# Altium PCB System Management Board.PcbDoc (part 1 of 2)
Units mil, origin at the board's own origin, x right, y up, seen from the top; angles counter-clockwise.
Board outline 5905.51 x 4330.71 mil, 4 copper layers (F.Cu, In1.Cu, In2.Cu, B.Cu); 241 components, 148 nets, 704 pads, 16 vias.
Unrouted connection lines stored in the file: 314.
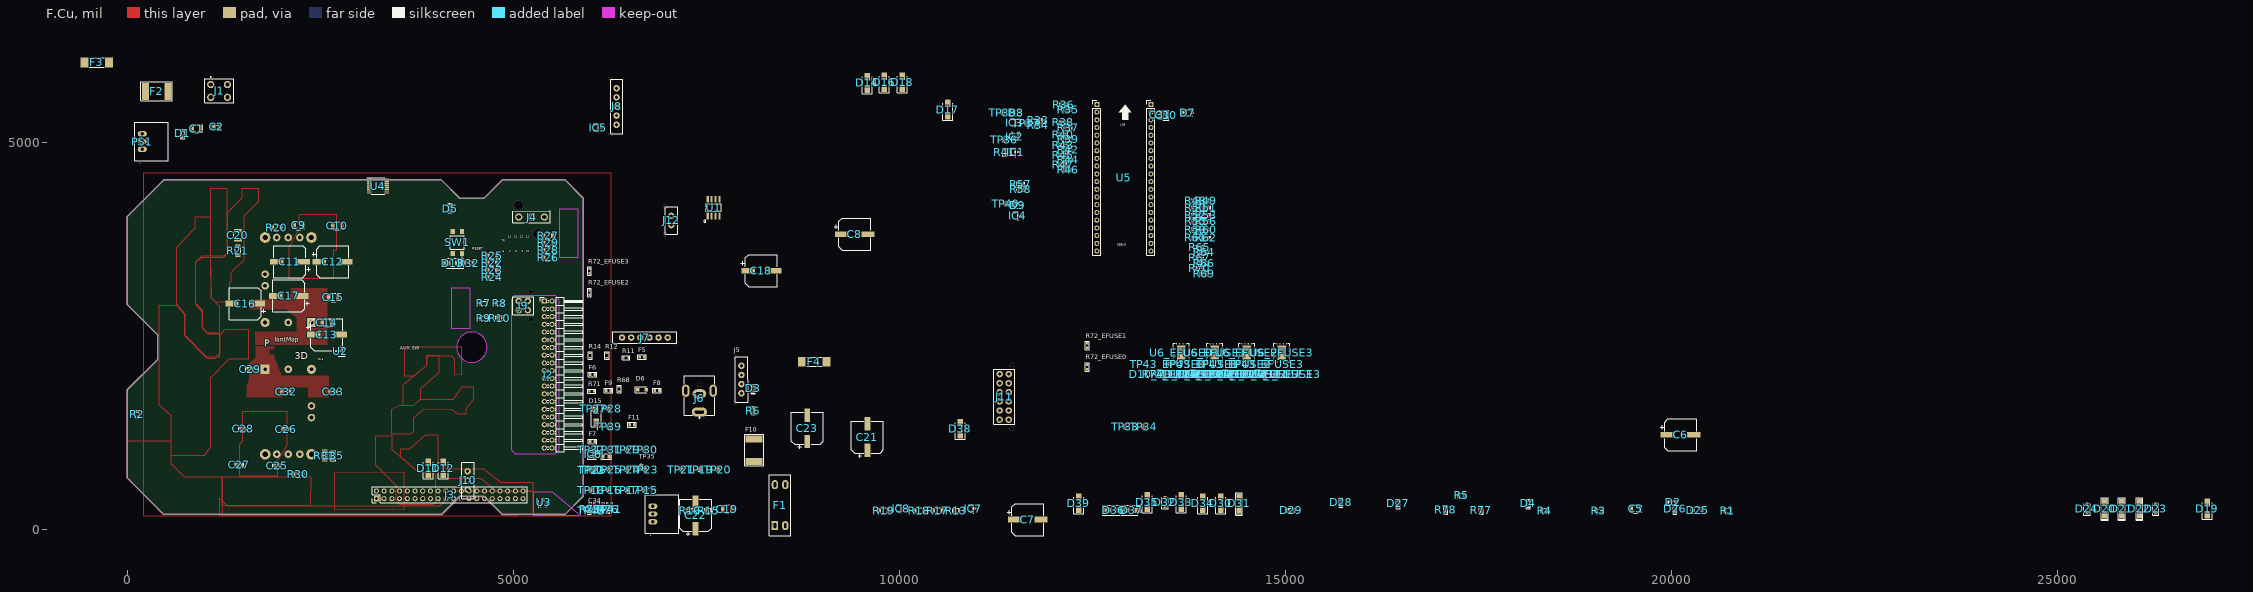
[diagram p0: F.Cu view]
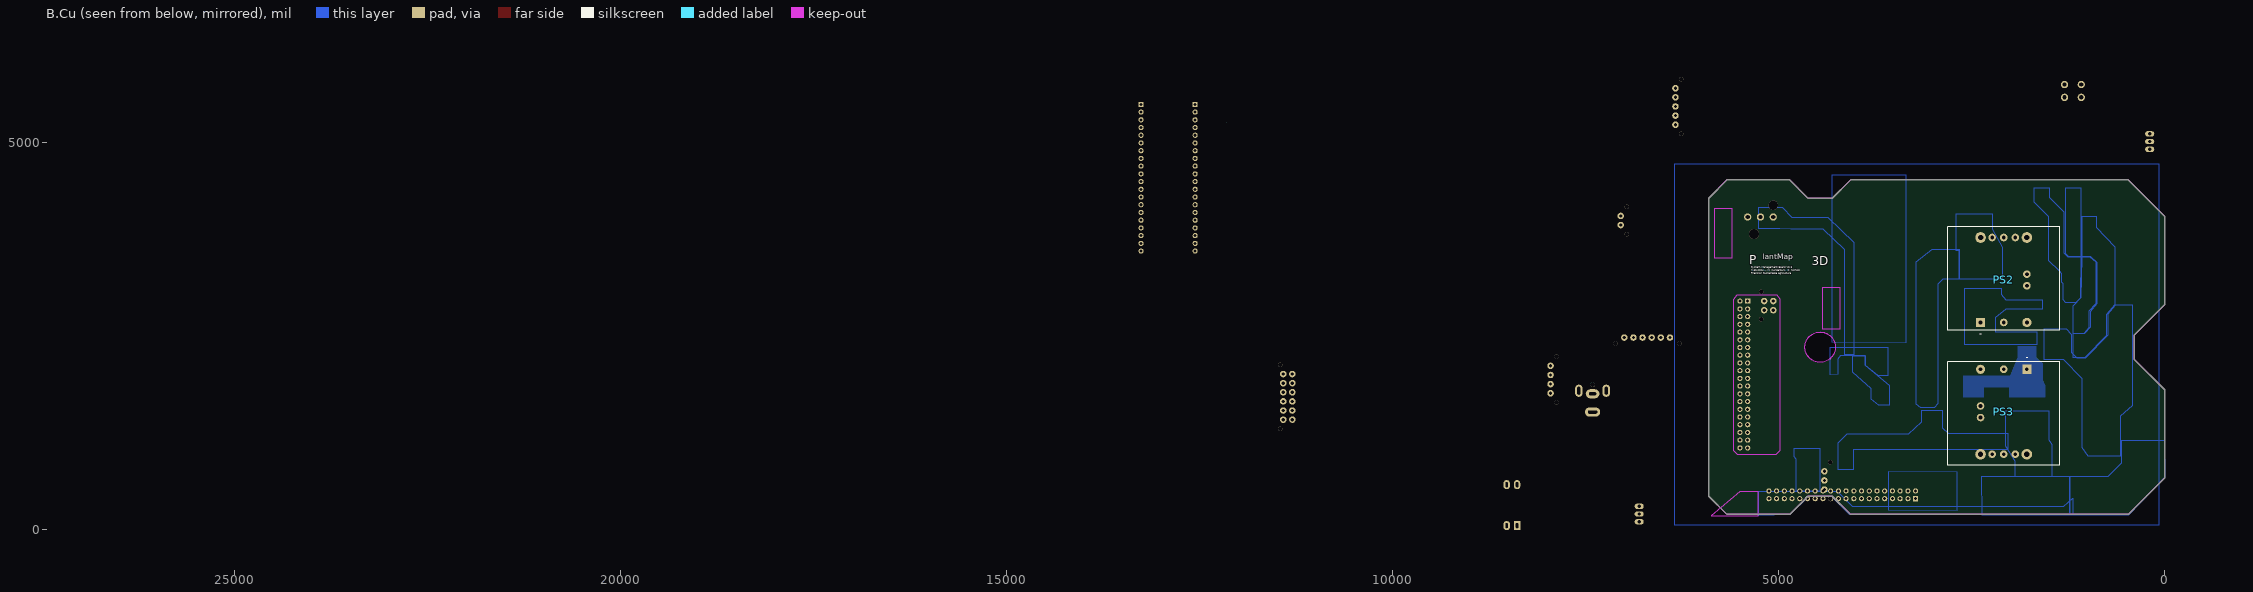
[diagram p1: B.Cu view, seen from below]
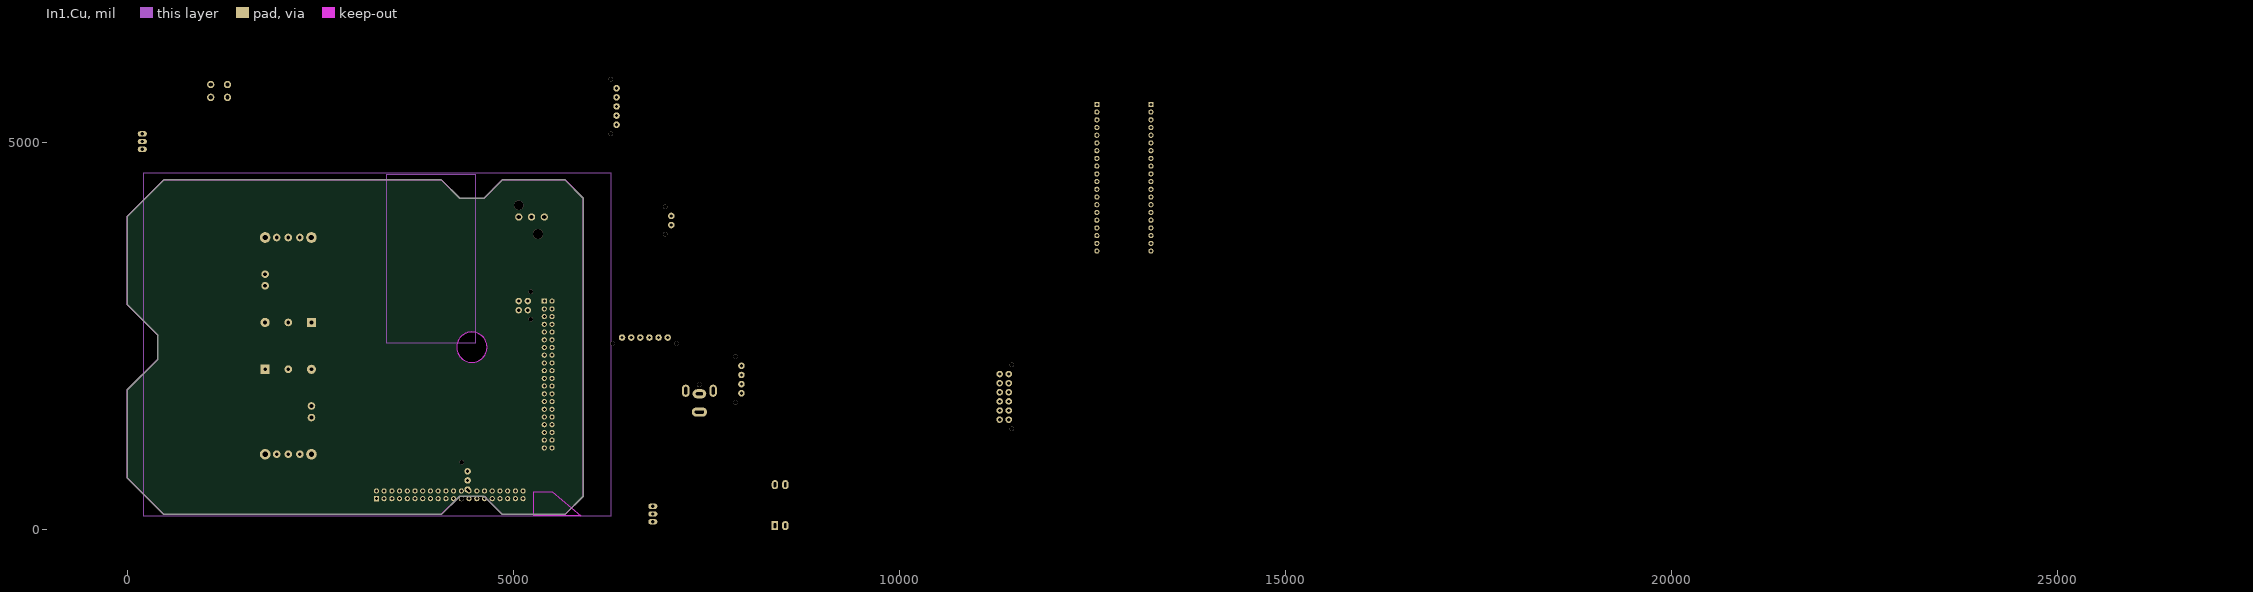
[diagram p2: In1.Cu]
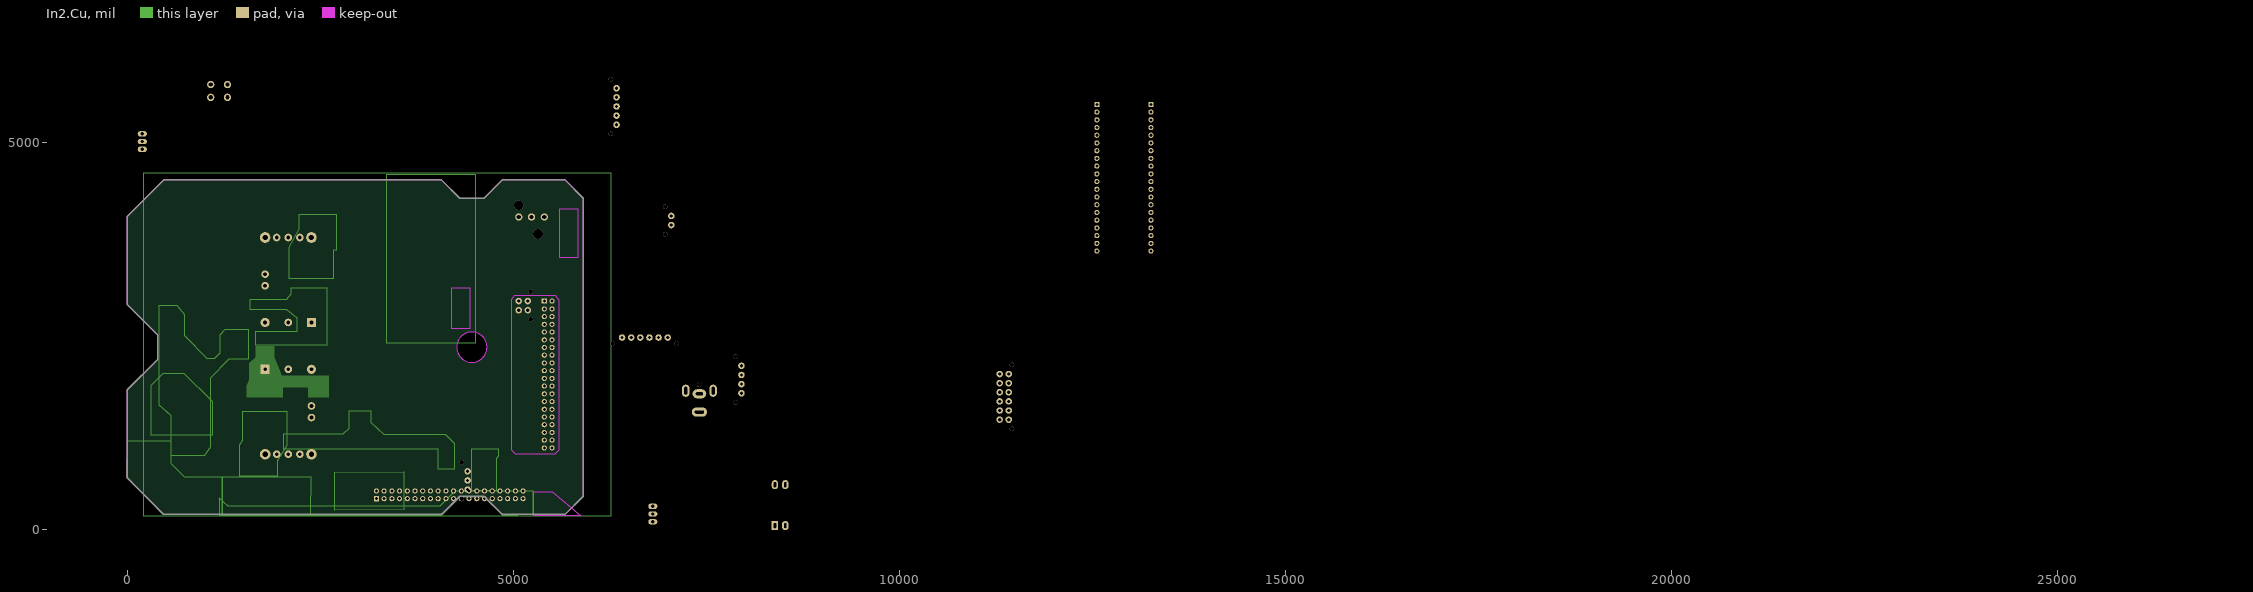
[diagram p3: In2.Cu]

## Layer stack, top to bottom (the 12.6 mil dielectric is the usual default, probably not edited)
F.Mask: solder mask 0.4, Solder Resist, Dk 3.5
F.Cu: signal copper 1.4
Dielectric 1: dielectric 12.6, FR-4, Dk 4.8
In1.Cu: signal copper 1.4
Dielectric2: dielectric 12.6, FR-4, Dk 4.8
In2.Cu: signal copper 1.4
Dielectric3: dielectric 12.6, FR-4, Dk 4.8
B.Cu: signal copper 1.4
B.Mask: solder mask 0.4, Solder Resist, Dk 3.5

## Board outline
4307.02,426.04 4621.98,426.04 4858.2,189.82 5671.85,189.82 5908.07,426.04 5908.07,4284.31 5671.85,4520.53 4858.2,4520.53 4621.98,4284.31 4307.02,4284.31 4070.8,4520.53 475,4520.53 2.56,4048.09 2.56,2906.36 396.26,2512.65 396.26,2197.69 2.56,1803.99 2.56,662.26 475,189.82 4070.8,189.82 4307.02,426.04
cut-out: 4267.23,2355.17 4268.92,2329.43 4273.95,2304.12 4282.24,2279.68 4293.66,2256.54 4307.99,2235.08 4325.01,2215.68 4344.41,2198.67 4365.86,2184.33 4389.01,2172.92 4413.44,2164.62 4438.75,2159.59 4464.5,2157.9 4490.25,2159.59 4515.56,2164.62 4539.99,2172.92 4563.14,2184.33 4584.59,2198.67 4603.99,2215.68 4621.01,2235.08 4635.34,2256.54 4646.76,2279.68 4655.05,2304.12 4660.09,2329.43 4661.77,2355.17 4660.09,2380.92 4655.05,2406.23 4646.76,2430.67 4635.34,2453.81 4621.01,2475.27 4603.99,2494.67 4584.59,2511.68 4563.14,2526.02 4539.99,2537.43 4515.56,2545.73 4490.25,2550.76 4464.5,2552.45 4438.75,2550.76 4413.44,2545.73 4389.01,2537.43 4365.86,2526.02 4344.41,2511.68 4325.01,2494.67 4307.99,2475.27 4293.66,2453.81 4282.24,2430.67 4273.95,2406.23 4268.92,2380.92 4267.23,2355.17

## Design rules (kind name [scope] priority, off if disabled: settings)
Clearance "Clearence 0.254_Polygon" [InNamedPolygon('F.Cu-/5V Intermediate') OR InNamedPolygon('F.Cu-/i3_Vin') OR InNamedPolygon('F.Cu-/SWITCH PWR OUT PROT') OR InNamedPolygon('F.Cu-GND') OR InNamedPolygon('In2.Cu-GND') OR InNamedPolygon('B.Cu-GND') OR InNamedPolygon('F.Cu-/15v PWR') OR InNamedPolygon('In2.Cu-/15v PWR') OR InNamedPolygon('B.Cu-/15v PWR') OR InNamedPolygon('F.Cu-GND-1') OR InNamedPolygon('In2.Cu-GND-1') OR InNamedPolygon('B.Cu-GND-1') OR InNamedPolygon('F.Cu-/48V PWR') OR InNamedPolygon('In2.Cu-/48V PWR') OR InNamedPolygon('B.Cu-/48V PWR') OR InNamedPolygon('F.Cu-/V_batt+') OR InNamedPolygon('In2.Cu-/V_batt+') OR InNamedPolygon('B.Cu-/V_batt+') OR InNamedPolygon('F.Cu-/V_batt+ PROT') OR InNamedPolygon('In2.Cu-/V_batt+ PROT') OR InNamedPolygon('B.Cu-/V_batt+ PROT') OR InNamedPolygon('F.Cu-/V_batt+ PROT SW') OR InNamedPolygon('In2.Cu-/V_batt+ PROT SW') OR InNamedPolygon('B.Cu-/V_batt+ PROT SW') OR InNamedPolygon('F.Cu-/CPS_IN_PROT') OR InNamedPolygon('In2.Cu-/CPS_IN_PROT') OR InNamedPolygon('B.Cu-/CPS_IN_PROT') OR InNamedPolygon('F.Cu-/V_batt+ PROT-1') OR InNamedPolygon('In2.Cu-/V_batt+ PROT-1') OR InNamedPolygon('B.Cu-/V_batt+ PROT-1') OR InNamedPolygon('F.Cu-/PSPS_IN_PROT') OR InNamedPolygon('In2.Cu-/PSPS_IN_PROT') OR InNamedPolygon('B.Cu-/PSPS_IN_PROT') OR InNamedPolygon('F.Cu-/15V Aux PWR OUT PROT') OR InNamedPolygon('B.Cu-/15V Aux PWR OUT PROT') OR InNamedPolygon('F.Cu-/LIGHT BANK A PROT') OR InNamedPolygon('B.Cu-/LIGHT BANK A PROT') OR InNamedPolygon('F.Cu-/LIGHT BANK A PROT SW') OR InNamedPolygon('B.Cu-/LIGHT BANK A PROT SW') OR InNamedPolygon('F.Cu-/LIGHT BANK B PROT SW') OR InNamedPolygon('B.Cu-/LIGHT BANK B PROT SW') OR InNamedPolygon('F.Cu-/COMP PWR OUT PROT') OR InNamedPolygon('B.Cu-/COMP PWR OUT PROT') OR InNamedPolygon('F.Cu-/LIGHT BANK B PROT') OR InNamedPolygon('B.Cu-/LIGHT BANK B PROT') OR InNamedPolygon('In1.Cu-GND') OR InNamedPolygon('In2.Cu-GND-3') OR InNamedPolygon('In2.Cu-/48V Aux PWR OUT PROT') OR InNamedPolygon('B.Cu-/48V Aux PWR OUT PROT') OR InNamedPolygon('In2.Cu-/48V PWR-1') OR InNamedPolygon('B.Cu-/48V PWR-1') OR InNamedPolygon('B.Cu-/COMP PWR OUT PROT-1') OR InNamedPolygon('B.Cu-/15v PWR-1')] p1: gap=10 ignorepadtopadclearanceinfootprint=FALSE
Clearance "Clearence 0.25_Polygon" [InNamedPolygon('In1.Cu-GND-1') OR InNamedPolygon('In2.Cu-GND-2') OR InNamedPolygon('B.Cu-GND-2')] p2: gap=9.84 ignorepadtopadclearanceinfootprint=FALSE
ComponentClearance [All] p1: gap=2.36 collisioncheckmode=3 verticalgap=2.36 showdistances=FALSE
HoleSize [All] p1: absolutevalues=TRUE maxlimit=157.48 minlimit=1 maxpercent=80.000 minpercent=20.000
MinimumSolderMaskSliver [All] p1: minsoldermaskwidth=0
PolygonConnect "Polygon_B.Cu-/15v PWR-1_ConnectDirect" [IsNamedPolygon('B.Cu-/15v PWR-1')] p1: connectstyle=Direct reliefconductorwidth=10 reliefentries=4 polygonreliefangle="90 Angle" airgapwidth=10
PolygonConnect "Polygon_B.Cu-/COMP PWR OUT PROT-1_ConnectDirect" [IsNamedPolygon('B.Cu-/COMP PWR OUT PROT-1')] p2: connectstyle=Direct reliefconductorwidth=10 reliefentries=4 polygonreliefangle="90 Angle" airgapwidth=10
PolygonConnect "Polygon_B.Cu-/48V PWR-1_ConnectDirect" [IsNamedPolygon('B.Cu-/48V PWR-1') vs IsVia] p3: connectstyle=Direct reliefconductorwidth=10 reliefentries=4 polygonreliefangle="90 Angle" airgapwidth=10
PolygonConnect "Polygon_B.Cu-/48V PWR-1_ConnectRelief45" [IsNamedPolygon('B.Cu-/48V PWR-1') vs (IsThruPin or IsSMTPin) and (PadShape_AllLayers = 'Round')] p4: connectstyle=Relief reliefconductorwidth=19.68 reliefentries=4 polygonreliefangle="45 Angle" airgapwidth=19.68
PolygonConnect "Polygon_B.Cu-/48V PWR-1_ConnectRelief90" [IsNamedPolygon('B.Cu-/48V PWR-1') vs (IsThruPin or IsSMTPin) and (PadShape_AllLayers <> 'Round')] p5: connectstyle=Relief reliefconductorwidth=19.68 reliefentries=4 polygonreliefangle="90 Angle" airgapwidth=19.68
PolygonConnect "Polygon_In2.Cu-/48V PWR-1_ConnectDirect" [IsNamedPolygon('In2.Cu-/48V PWR-1') vs IsVia] p6: connectstyle=Direct reliefconductorwidth=10 reliefentries=4 polygonreliefangle="90 Angle" airgapwidth=10
PolygonConnect "Polygon_In2.Cu-/48V PWR-1_ConnectRelief45" [IsNamedPolygon('In2.Cu-/48V PWR-1') vs (IsThruPin or IsSMTPin) and (PadShape_AllLayers = 'Round')] p7: connectstyle=Relief reliefconductorwidth=19.68 reliefentries=4 polygonreliefangle="45 Angle" airgapwidth=19.68
PolygonConnect "Polygon_In2.Cu-/48V PWR-1_ConnectRelief90" [IsNamedPolygon('In2.Cu-/48V PWR-1') vs (IsThruPin or IsSMTPin) and (PadShape_AllLayers <> 'Round')] p8: connectstyle=Relief reliefconductorwidth=19.68 reliefentries=4 polygonreliefangle="90 Angle" airgapwidth=19.68
PolygonConnect "Polygon_B.Cu-/48V Aux PWR OUT PROT_ConnectDirect" [IsNamedPolygon('B.Cu-/48V Aux PWR OUT PROT') vs IsVia] p9: connectstyle=Direct reliefconductorwidth=10 reliefentries=4 polygonreliefangle="90 Angle" airgapwidth=10
PolygonConnect "Polygon_B.Cu-/48V Aux PWR OUT PROT_ConnectRelief45" [IsNamedPolygon('B.Cu-/48V Aux PWR OUT PROT') vs (IsThruPin or IsSMTPin) and (PadShape_AllLayers = 'Round')] p10: connectstyle=Relief reliefconductorwidth=19.68 reliefentries=4 polygonreliefangle="45 Angle" airgapwidth=19.68
PolygonConnect "Polygon_B.Cu-/48V Aux PWR OUT PROT_ConnectRelief90" [IsNamedPolygon('B.Cu-/48V Aux PWR OUT PROT') vs (IsThruPin or IsSMTPin) and (PadShape_AllLayers <> 'Round')] p11: connectstyle=Relief reliefconductorwidth=19.68 reliefentries=4 polygonreliefangle="90 Angle" airgapwidth=19.68
PolygonConnect "Polygon_In2.Cu-/48V Aux PWR OUT PROT_ConnectDirect" [IsNamedPolygon('In2.Cu-/48V Aux PWR OUT PROT') vs IsVia] p12: connectstyle=Direct reliefconductorwidth=10 reliefentries=4 polygonreliefangle="90 Angle" airgapwidth=10
PolygonConnect "Polygon_In2.Cu-/48V Aux PWR OUT PROT_ConnectRelief45" [IsNamedPolygon('In2.Cu-/48V Aux PWR OUT PROT') vs (IsThruPin or IsSMTPin) and (PadShape_AllLayers = 'Round')] p13: connectstyle=Relief reliefconductorwidth=19.68 reliefentries=4 polygonreliefangle="45 Angle" airgapwidth=19.68
PolygonConnect "Polygon_In2.Cu-/48V Aux PWR OUT PROT_ConnectRelief90" [IsNamedPolygon('In2.Cu-/48V Aux PWR OUT PROT') vs (IsThruPin or IsSMTPin) and (PadShape_AllLayers <> 'Round')] p14: connectstyle=Relief reliefconductorwidth=19.68 reliefentries=4 polygonreliefangle="90 Angle" airgapwidth=19.68
PolygonConnect Polygon_In2.Cu-GND-3_ConnectDirect [IsNamedPolygon('In2.Cu-GND-3') vs IsVia] p15: connectstyle=Direct reliefconductorwidth=10 reliefentries=4 polygonreliefangle="90 Angle" airgapwidth=10
PolygonConnect Polygon_In2.Cu-GND-3_ConnectRelief45 [IsNamedPolygon('In2.Cu-GND-3') vs (IsThruPin or IsSMTPin) and (PadShape_AllLayers = 'Round')] p16: connectstyle=Relief reliefconductorwidth=19.68 reliefentries=4 polygonreliefangle="45 Angle" airgapwidth=19.68
PolygonConnect Polygon_In2.Cu-GND-3_ConnectRelief90 [IsNamedPolygon('In2.Cu-GND-3') vs (IsThruPin or IsSMTPin) and (PadShape_AllLayers <> 'Round')] p17: connectstyle=Relief reliefconductorwidth=19.68 reliefentries=4 polygonreliefangle="90 Angle" airgapwidth=19.68
PolygonConnect Polygon_B.Cu-GND-2_ConnectDirect [IsNamedPolygon('B.Cu-GND-2') vs IsVia] p18: connectstyle=Direct reliefconductorwidth=10 reliefentries=4 polygonreliefangle="90 Angle" airgapwidth=10
PolygonConnect Polygon_B.Cu-GND-2_ConnectRelief45 [IsNamedPolygon('B.Cu-GND-2') vs (IsThruPin or IsSMTPin) and (PadShape_AllLayers = 'Round')] p19: connectstyle=Relief reliefconductorwidth=20 reliefentries=4 polygonreliefangle="45 Angle" airgapwidth=20
PolygonConnect Polygon_B.Cu-GND-2_ConnectRelief90 [IsNamedPolygon('B.Cu-GND-2') vs (IsThruPin or IsSMTPin) and (PadShape_AllLayers <> 'Round')] p20: connectstyle=Relief reliefconductorwidth=20 reliefentries=4 polygonreliefangle="90 Angle" airgapwidth=20
PolygonConnect Polygon_In2.Cu-GND-2_ConnectDirect [IsNamedPolygon('In2.Cu-GND-2') vs IsVia] p21: connectstyle=Direct reliefconductorwidth=10 reliefentries=4 polygonreliefangle="90 Angle" airgapwidth=10
PolygonConnect Polygon_In2.Cu-GND-2_ConnectRelief45 [IsNamedPolygon('In2.Cu-GND-2') vs (IsThruPin or IsSMTPin) and (PadShape_AllLayers = 'Round')] p22: connectstyle=Relief reliefconductorwidth=20 reliefentries=4 polygonreliefangle="45 Angle" airgapwidth=20
PolygonConnect Polygon_In2.Cu-GND-2_ConnectRelief90 [IsNamedPolygon('In2.Cu-GND-2') vs (IsThruPin or IsSMTPin) and (PadShape_AllLayers <> 'Round')] p23: connectstyle=Relief reliefconductorwidth=20 reliefentries=4 polygonreliefangle="90 Angle" airgapwidth=20
PolygonConnect Polygon_In1.Cu-GND-1_ConnectDirect [IsNamedPolygon('In1.Cu-GND-1') vs IsVia] p24: connectstyle=Direct reliefconductorwidth=10 reliefentries=4 polygonreliefangle="90 Angle" airgapwidth=10
PolygonConnect Polygon_In1.Cu-GND-1_ConnectRelief45 [IsNamedPolygon('In1.Cu-GND-1') vs (IsThruPin or IsSMTPin) and (PadShape_AllLayers = 'Round')] p25: connectstyle=Relief reliefconductorwidth=20 reliefentries=4 polygonreliefangle="45 Angle" airgapwidth=20
PolygonConnect Polygon_In1.Cu-GND-1_ConnectRelief90 [IsNamedPolygon('In1.Cu-GND-1') vs (IsThruPin or IsSMTPin) and (PadShape_AllLayers <> 'Round')] p26: connectstyle=Relief reliefconductorwidth=20 reliefentries=4 polygonreliefangle="90 Angle" airgapwidth=20
PolygonConnect Polygon_In1.Cu-GND_ConnectDirect [IsNamedPolygon('In1.Cu-GND')] p27: connectstyle=Direct reliefconductorwidth=10 reliefentries=4 polygonreliefangle="90 Angle" airgapwidth=10
PolygonConnect "Polygon_B.Cu-/LIGHT BANK B PROT_ConnectDirect" [IsNamedPolygon('B.Cu-/LIGHT BANK B PROT')] p28: connectstyle=Direct reliefconductorwidth=10 reliefentries=4 polygonreliefangle="90 Angle" airgapwidth=10
PolygonConnect "Polygon_F.Cu-/LIGHT BANK B PROT_ConnectDirect" [IsNamedPolygon('F.Cu-/LIGHT BANK B PROT')] p29: connectstyle=Direct reliefconductorwidth=10 reliefentries=4 polygonreliefangle="90 Angle" airgapwidth=10
PolygonConnect "Polygon_B.Cu-/COMP PWR OUT PROT_ConnectDirect" [IsNamedPolygon('B.Cu-/COMP PWR OUT PROT') vs IsVia] p30: connectstyle=Direct reliefconductorwidth=10 reliefentries=4 polygonreliefangle="90 Angle" airgapwidth=10
PolygonConnect "Polygon_B.Cu-/COMP PWR OUT PROT_ConnectRelief45" [IsNamedPolygon('B.Cu-/COMP PWR OUT PROT') vs (IsThruPin or IsSMTPin) and (PadShape_AllLayers = 'Round')] p31: connectstyle=Relief reliefconductorwidth=19.68 reliefentries=4 polygonreliefangle="45 Angle" airgapwidth=19.68
PolygonConnect "Polygon_B.Cu-/COMP PWR OUT PROT_ConnectRelief90" [IsNamedPolygon('B.Cu-/COMP PWR OUT PROT') vs (IsThruPin or IsSMTPin) and (PadShape_AllLayers <> 'Round')] p32: connectstyle=Relief reliefconductorwidth=19.68 reliefentries=4 polygonreliefangle="90 Angle" airgapwidth=19.68
PolygonConnect "Polygon_F.Cu-/COMP PWR OUT PROT_ConnectDirect" [IsNamedPolygon('F.Cu-/COMP PWR OUT PROT') vs IsVia] p33: connectstyle=Direct reliefconductorwidth=10 reliefentries=4 polygonreliefangle="90 Angle" airgapwidth=10
PolygonConnect "Polygon_F.Cu-/COMP PWR OUT PROT_ConnectRelief45" [IsNamedPolygon('F.Cu-/COMP PWR OUT PROT') vs (IsThruPin or IsSMTPin) and (PadShape_AllLayers = 'Round')] p34: connectstyle=Relief reliefconductorwidth=19.68 reliefentries=4 polygonreliefangle="45 Angle" airgapwidth=19.68
PolygonConnect "Polygon_F.Cu-/COMP PWR OUT PROT_ConnectRelief90" [IsNamedPolygon('F.Cu-/COMP PWR OUT PROT') vs (IsThruPin or IsSMTPin) and (PadShape_AllLayers <> 'Round')] p35: connectstyle=Relief reliefconductorwidth=19.68 reliefentries=4 polygonreliefangle="90 Angle" airgapwidth=19.68
PolygonConnect "Polygon_B.Cu-/LIGHT BANK B PROT SW_ConnectDirect" [IsNamedPolygon('B.Cu-/LIGHT BANK B PROT SW')] p36: connectstyle=Direct reliefconductorwidth=10 reliefentries=4 polygonreliefangle="90 Angle" airgapwidth=10
PolygonConnect "Polygon_F.Cu-/LIGHT BANK B PROT SW_ConnectDirect" [IsNamedPolygon('F.Cu-/LIGHT BANK B PROT SW')] p37: connectstyle=Direct reliefconductorwidth=10 reliefentries=4 polygonreliefangle="90 Angle" airgapwidth=10
PolygonConnect "Polygon_B.Cu-/LIGHT BANK A PROT SW_ConnectDirect" [IsNamedPolygon('B.Cu-/LIGHT BANK A PROT SW')] p38: connectstyle=Direct reliefconductorwidth=10 reliefentries=4 polygonreliefangle="90 Angle" airgapwidth=10
PolygonConnect "Polygon_F.Cu-/LIGHT BANK A PROT SW_ConnectDirect" [IsNamedPolygon('F.Cu-/LIGHT BANK A PROT SW')] p39: connectstyle=Direct reliefconductorwidth=10 reliefentries=4 polygonreliefangle="90 Angle" airgapwidth=10
PolygonConnect "Polygon_B.Cu-/LIGHT BANK A PROT_ConnectDirect" [IsNamedPolygon('B.Cu-/LIGHT BANK A PROT')] p40: connectstyle=Direct reliefconductorwidth=10 reliefentries=4 polygonreliefangle="90 Angle" airgapwidth=10
PolygonConnect "Polygon_F.Cu-/LIGHT BANK A PROT_ConnectDirect" [IsNamedPolygon('F.Cu-/LIGHT BANK A PROT')] p41: connectstyle=Direct reliefconductorwidth=10 reliefentries=4 polygonreliefangle="90 Angle" airgapwidth=10
PolygonConnect "Polygon_B.Cu-/15V Aux PWR OUT PROT_ConnectDirect" [IsNamedPolygon('B.Cu-/15V Aux PWR OUT PROT') vs IsVia] p42: connectstyle=Direct reliefconductorwidth=10 reliefentries=4 polygonreliefangle="90 Angle" airgapwidth=10
PolygonConnect "Polygon_B.Cu-/15V Aux PWR OUT PROT_ConnectRelief45" [IsNamedPolygon('B.Cu-/15V Aux PWR OUT PROT') vs (IsThruPin or IsSMTPin) and (PadShape_AllLayers = 'Round')] p43: connectstyle=Relief reliefconductorwidth=19.68 reliefentries=4 polygonreliefangle="45 Angle" airgapwidth=19.68
PolygonConnect "Polygon_B.Cu-/15V Aux PWR OUT PROT_ConnectRelief90" [IsNamedPolygon('B.Cu-/15V Aux PWR OUT PROT') vs (IsThruPin or IsSMTPin) and (PadShape_AllLayers <> 'Round')] p44: connectstyle=Relief reliefconductorwidth=19.68 reliefentries=4 polygonreliefangle="90 Angle" airgapwidth=19.68
PolygonConnect "Polygon_F.Cu-/15V Aux PWR OUT PROT_ConnectDirect" [IsNamedPolygon('F.Cu-/15V Aux PWR OUT PROT') vs IsVia] p45: connectstyle=Direct reliefconductorwidth=10 reliefentries=4 polygonreliefangle="90 Angle" airgapwidth=10
PolygonConnect "Polygon_F.Cu-/15V Aux PWR OUT PROT_ConnectRelief45" [IsNamedPolygon('F.Cu-/15V Aux PWR OUT PROT') vs (IsThruPin or IsSMTPin) and (PadShape_AllLayers = 'Round')] p46: connectstyle=Relief reliefconductorwidth=19.68 reliefentries=4 polygonreliefangle="45 Angle" airgapwidth=19.68
PolygonConnect "Polygon_F.Cu-/15V Aux PWR OUT PROT_ConnectRelief90" [IsNamedPolygon('F.Cu-/15V Aux PWR OUT PROT') vs (IsThruPin or IsSMTPin) and (PadShape_AllLayers <> 'Round')] p47: connectstyle=Relief reliefconductorwidth=19.68 reliefentries=4 polygonreliefangle="90 Angle" airgapwidth=19.68
PolygonConnect Polygon_B.Cu-/PSPS_IN_PROT_ConnectDirect [IsNamedPolygon('B.Cu-/PSPS_IN_PROT')] p48: connectstyle=Direct reliefconductorwidth=10 reliefentries=4 polygonreliefangle="90 Angle" airgapwidth=10
PolygonConnect Polygon_In2.Cu-/PSPS_IN_PROT_ConnectDirect [IsNamedPolygon('In2.Cu-/PSPS_IN_PROT')] p49: connectstyle=Direct reliefconductorwidth=10 reliefentries=4 polygonreliefangle="90 Angle" airgapwidth=10
PolygonConnect Polygon_F.Cu-/PSPS_IN_PROT_ConnectDirect [IsNamedPolygon('F.Cu-/PSPS_IN_PROT')] p50: connectstyle=Direct reliefconductorwidth=10 reliefentries=4 polygonreliefangle="90 Angle" airgapwidth=10
PolygonConnect "Polygon_B.Cu-/V_batt+ PROT-1_ConnectDirect" [IsNamedPolygon('B.Cu-/V_batt+ PROT-1')] p51: connectstyle=Direct reliefconductorwidth=10 reliefentries=4 polygonreliefangle="90 Angle" airgapwidth=10
PolygonConnect "Polygon_In2.Cu-/V_batt+ PROT-1_ConnectDirect" [IsNamedPolygon('In2.Cu-/V_batt+ PROT-1')] p52: connectstyle=Direct reliefconductorwidth=10 reliefentries=4 polygonreliefangle="90 Angle" airgapwidth=10
PolygonConnect "Polygon_F.Cu-/V_batt+ PROT-1_ConnectDirect" [IsNamedPolygon('F.Cu-/V_batt+ PROT-1')] p53: connectstyle=Direct reliefconductorwidth=10 reliefentries=4 polygonreliefangle="90 Angle" airgapwidth=10
PolygonConnect Polygon_B.Cu-/CPS_IN_PROT_ConnectDirect [IsNamedPolygon('B.Cu-/CPS_IN_PROT')] p54: connectstyle=Direct reliefconductorwidth=10 reliefentries=4 polygonreliefangle="90 Angle" airgapwidth=10
PolygonConnect Polygon_In2.Cu-/CPS_IN_PROT_ConnectDirect [IsNamedPolygon('In2.Cu-/CPS_IN_PROT')] p55: connectstyle=Direct reliefconductorwidth=10 reliefentries=4 polygonreliefangle="90 Angle" airgapwidth=10
PolygonConnect Polygon_F.Cu-/CPS_IN_PROT_ConnectDirect [IsNamedPolygon('F.Cu-/CPS_IN_PROT')] p56: connectstyle=Direct reliefconductorwidth=10 reliefentries=4 polygonreliefangle="90 Angle" airgapwidth=10
PolygonConnect "Polygon_B.Cu-/V_batt+ PROT SW_ConnectDirect" [IsNamedPolygon('B.Cu-/V_batt+ PROT SW')] p57: connectstyle=Direct reliefconductorwidth=10 reliefentries=4 polygonreliefangle="90 Angle" airgapwidth=10
PolygonConnect "Polygon_In2.Cu-/V_batt+ PROT SW_ConnectDirect" [IsNamedPolygon('In2.Cu-/V_batt+ PROT SW')] p58: connectstyle=Direct reliefconductorwidth=10 reliefentries=4 polygonreliefangle="90 Angle" airgapwidth=10
PolygonConnect "Polygon_F.Cu-/V_batt+ PROT SW_ConnectDirect" [IsNamedPolygon('F.Cu-/V_batt+ PROT SW')] p59: connectstyle=Direct reliefconductorwidth=10 reliefentries=4 polygonreliefangle="90 Angle" airgapwidth=10
PolygonConnect "Polygon_B.Cu-/V_batt+ PROT_ConnectDirect" [IsNamedPolygon('B.Cu-/V_batt+ PROT')] p60: connectstyle=Direct reliefconductorwidth=10 reliefentries=4 polygonreliefangle="90 Angle" airgapwidth=10
PolygonConnect "Polygon_In2.Cu-/V_batt+ PROT_ConnectDirect" [IsNamedPolygon('In2.Cu-/V_batt+ PROT')] p61: connectstyle=Direct reliefconductorwidth=10 reliefentries=4 polygonreliefangle="90 Angle" airgapwidth=10
PolygonConnect "Polygon_F.Cu-/V_batt+ PROT_ConnectDirect" [IsNamedPolygon('F.Cu-/V_batt+ PROT')] p62: connectstyle=Direct reliefconductorwidth=10 reliefentries=4 polygonreliefangle="90 Angle" airgapwidth=10
PolygonConnect Polygon_B.Cu-/V_batt+_ConnectDirect [IsNamedPolygon('B.Cu-/V_batt+')] p63: connectstyle=Direct reliefconductorwidth=10 reliefentries=4 polygonreliefangle="90 Angle" airgapwidth=10
PolygonConnect Polygon_In2.Cu-/V_batt+_ConnectDirect [IsNamedPolygon('In2.Cu-/V_batt+')] p64: connectstyle=Direct reliefconductorwidth=10 reliefentries=4 polygonreliefangle="90 Angle" airgapwidth=10
PolygonConnect Polygon_F.Cu-/V_batt+_ConnectDirect [IsNamedPolygon('F.Cu-/V_batt+')] p65: connectstyle=Direct reliefconductorwidth=10 reliefentries=4 polygonreliefangle="90 Angle" airgapwidth=10
PolygonConnect "Polygon_B.Cu-/48V PWR_ConnectDirect" [IsNamedPolygon('B.Cu-/48V PWR')] p66: connectstyle=Direct reliefconductorwidth=10 reliefentries=4 polygonreliefangle="90 Angle" airgapwidth=10
PolygonConnect "Polygon_In2.Cu-/48V PWR_ConnectDirect" [IsNamedPolygon('In2.Cu-/48V PWR')] p67: connectstyle=Direct reliefconductorwidth=10 reliefentries=4 polygonreliefangle="90 Angle" airgapwidth=10
PolygonConnect "Polygon_F.Cu-/48V PWR_ConnectDirect" [IsNamedPolygon('F.Cu-/48V PWR')] p68: connectstyle=Direct reliefconductorwidth=10 reliefentries=4 polygonreliefangle="90 Angle" airgapwidth=10
PolygonConnect Polygon_B.Cu-GND-1_ConnectDirect [IsNamedPolygon('B.Cu-GND-1')] p69: connectstyle=Direct reliefconductorwidth=10 reliefentries=4 polygonreliefangle="90 Angle" airgapwidth=10
PolygonConnect Polygon_In2.Cu-GND-1_ConnectDirect [IsNamedPolygon('In2.Cu-GND-1')] p70: connectstyle=Direct reliefconductorwidth=10 reliefentries=4 polygonreliefangle="90 Angle" airgapwidth=10
PolygonConnect Polygon_F.Cu-GND-1_ConnectDirect [IsNamedPolygon('F.Cu-GND-1')] p71: connectstyle=Direct reliefconductorwidth=10 reliefentries=4 polygonreliefangle="90 Angle" airgapwidth=10
PolygonConnect "Polygon_B.Cu-/15v PWR_ConnectDirect" [IsNamedPolygon('B.Cu-/15v PWR')] p72: connectstyle=Direct reliefconductorwidth=10 reliefentries=4 polygonreliefangle="90 Angle" airgapwidth=10
PolygonConnect "Polygon_In2.Cu-/15v PWR_ConnectDirect" [IsNamedPolygon('In2.Cu-/15v PWR')] p73: connectstyle=Direct reliefconductorwidth=10 reliefentries=4 polygonreliefangle="90 Angle" airgapwidth=10
PolygonConnect "Polygon_F.Cu-/15v PWR_ConnectDirect" [IsNamedPolygon('F.Cu-/15v PWR')] p74: connectstyle=Direct reliefconductorwidth=10 reliefentries=4 polygonreliefangle="90 Angle" airgapwidth=10
PolygonConnect Polygon_B.Cu-GND_ConnectDirect [IsNamedPolygon('B.Cu-GND')] p75: connectstyle=Direct reliefconductorwidth=10 reliefentries=4 polygonreliefangle="90 Angle" airgapwidth=10
PolygonConnect Polygon_In2.Cu-GND_ConnectDirect [IsNamedPolygon('In2.Cu-GND')] p76: connectstyle=Direct reliefconductorwidth=10 reliefentries=4 polygonreliefangle="90 Angle" airgapwidth=10
PolygonConnect Polygon_F.Cu-GND_ConnectDirect [IsNamedPolygon('F.Cu-GND')] p77: connectstyle=Direct reliefconductorwidth=10 reliefentries=4 polygonreliefangle="90 Angle" airgapwidth=10
PolygonConnect "Polygon_F.Cu-/SWITCH PWR OUT PROT_ConnectDirect" [IsNamedPolygon('F.Cu-/SWITCH PWR OUT PROT')] p78: connectstyle=Direct reliefconductorwidth=10 reliefentries=4 polygonreliefangle="90 Angle" airgapwidth=10
PolygonConnect Polygon_F.Cu-/i3_Vin_ConnectDirect [IsNamedPolygon('F.Cu-/i3_Vin')] p79: connectstyle=Direct reliefconductorwidth=10 reliefentries=4 polygonreliefangle="90 Angle" airgapwidth=10
PolygonConnect "Polygon_F.Cu-/5V Intermediate_ConnectDirect" [IsNamedPolygon('F.Cu-/5V Intermediate')] p80: connectstyle=Direct reliefconductorwidth=10 reliefentries=4 polygonreliefangle="90 Angle" airgapwidth=10
RoomDefinition EFUSE1 [InComponentClass('EFUSE1')] p1: confinementstyle=ConfineIn formatcopy=TRUE lockcomponents=FALSE outline 12395.26,2306.57 12995.65,2306.57 12995.65,2552.63 12395.26,2552.63
RoomDefinition EFUSE0 [InComponentClass('EFUSE0')] p2: confinementstyle=ConfineIn formatcopy=TRUE lockcomponents=FALSE outline 12395.26,2030.98 13015.34,2030.98 13015.34,2277.04 12395.26,2277.04
RoomDefinition EFUSE2 [InComponentClass('EFUSE2')] p3: confinementstyle=ConfineIn formatcopy=TRUE lockcomponents=FALSE outline 14261.81,1909.45 14694.88,1909.45 14694.88,2431.1 14261.81,2431.1
RoomDefinition EFUSE3 [InComponentClass('EFUSE3')] p4: confinementstyle=ConfineIn formatcopy=TRUE lockcomponents=FALSE outline 14694.88,1909.45 15127.95,1909.45 15127.95,2431.1 14694.88,2431.1
RoutingVias [All] p1: holewidth=28 width=50 viastyle="Through Hole" minholewidth=28 minwidth=50 maxholewidth=28 maxwidth=50
SilkToSilkClearance [All] p1: silktosilkclearance=0
SilkToSolderMaskClearance [IsPad] p1: minsilkscreentomaskgap=0 clearancetoexposedcopper=TRUE
SolderMaskExpansion [All] p1: expansion=4 istentingtop=FALSE
SupplyNets "Schematic Supply Nets_5" [InNet('PICO_3V3')] p1: voltage=0.000
SupplyNets "Schematic Supply Nets_2" [InNet('+3V3')] p2: voltage=0.000
SupplyNets "Schematic Supply Nets_9" [InNet('+15V')] p3: voltage=0.000
SupplyNets "Schematic Supply Nets_8" [InNet('+24V')] p4: voltage=0.000
SupplyNets "Schematic Supply Nets_1" [InNet('+48V')] p5: voltage=0.000
SupplyNets "Schematic Supply Nets_4" [InNet('+5V')] p6: voltage=0.000
SupplyNets "Schematic Supply Nets" [InNet('GND')] p7: voltage=0.000
Width [All] p1: maxlimit=393.7 minlimit=9.84 preferedwidth=9.84 minimp=50.000000 maximp=50.000000 favimp=50.000000
25 further rules are at their usual default settings.

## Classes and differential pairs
component class "U_TEMPERATURE SENSORS": C33 F6 TP27 TP28 U2 U3
net class POE_OUT_[1..6]: POE_OUT_1 POE_OUT_2 POE_OUT_3 POE_OUT_4 POE_OUT_5 POE_OUT_6
net class CONTACTOR_OUT_[2..4]: CONTACTOR_OUT_2 CONTACTOR_OUT_3 CONTACTOR_OUT_4
net class CONTACTOR_CTRL_[1..4]: CONTACTOR_CTRL_1 CONTACTOR_CTRL_2 CONTACTOR_CTRL_3 CONTACTOR_CTRL_4
component class EFUSE3: D10_EFUSE3 R72_EFUSE3 R73_EFUSE3 R74_EFUSE3 TP43_EFUSE3 U6_EFUSE3
component class EFUSE2: D10_EFUSE2 R72_EFUSE2 R73_EFUSE2 R74_EFUSE2 TP43_EFUSE2 U6_EFUSE2
component class EFUSE1: D10_EFUSE1 R72_EFUSE1 R73_EFUSE1 R74_EFUSE1 TP43_EFUSE1 U6_EFUSE1
net class MUX_S[0..2]: MUX_S0 MUX_S1 MUX_S2
channel class EFUSE: EFUSE0 EFUSE1 EFUSE2 EFUSE3
component class "U_UART TO RS485": C25 C32 F10 R10 R16 R18 R20 R22 U1
component class "U_PICO MCU": C32 C33 D9 F8 F9 IC1 IC2 IC3 IC4 R35 R40 R42 R44 R46 R48 R50 R55 R57 R59 R61 R63 R65 R68 R69 R70 R75 SW1 TP33 TP34 TP35 U5
component class "U_OUTPUT CONNECTORS": D14 D16 D18 D21 D25 D28 D30 D33 D35 D39 F11 IC5 IC6 IC7 IC8 J4 J6 J7 J8 J9 J11 J12 R75 R76 R77 R78
component class "U_INPUT CONNECTORS": J1 J2 J3
component class "U_ANALOG MUX": C32 F7 R18 R20 R22 R24 R26 R28 R30 R35 R40 TP29 TP30 TP31 TP32 U4
component class "U_48V AND 15V PSU": C5 C10 C13 C14 C19 C24 C25 D1 D2 D3 D4 D5 F3 F4 PS2 PS3 R1 R2 R3 R4 R5 R6 R7 R8 R9 TP19 TP20 TP21 TP22 TP23 TP24 TP25 TP26
component class "U_5V0 PSU": C1 C2 C5 C10 F1 F2 PS1 TP15 TP16 TP17 TP18
component class "U_3V3 PSU": C32 C33 C34 C35 F10 PS4
component class EFUSE0: D10_EFUSE0 R72_EFUSE0 R73_EFUSE0 R74_EFUSE0 TP43_EFUSE0 U6_EFUSE0

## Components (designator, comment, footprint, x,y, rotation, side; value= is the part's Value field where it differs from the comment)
C1 "C" C_1210_3225Metric 901.93,5185 r0 top value=10uF
C2 "CL10B104KC8NNNC" C_0603 1160,5210 r0 top value=100nF
C3 "CL21B106KPQNFNE" C_0805 6204.31,938.46 r0 top value=10uF
C4 "CL10B104KC8NNNC" C_0603 6017.31,928.62 r0 top value=100nF
C5 "Comment" C_1210_3225Metric 19535,260 r0 top value=10uF
C6 "Comment" CP_Elec_10x12.6 20118.11,1220.47 r0 top value=100uF
C7 "Comment" CP_Elec_10x12.6 11663.39,122.6 r0 top value=100uF
C8 "Comment" CP_Elec_10x12.6 9423.23,3818.9 r0 top value=100uF
C9 "Comment" C_1210_3225METRIC 2220.08,3931.56 r180 top value=10uF
C10 "Comment" C_1210_3225Metric 2720.08,3925.65 r0 top value=10uF
C11 "Comment" CP_ELEC_10X12.6 2107.87,3463.05 r180 top value=180uF
C12 "Comment" CP_ELEC_10X12.6 2661.02,3461.09 r0 top value=180uF
C13 "Comment" CP_Elec_10x12.6 2587.2,2518.17 r0 top value=180uF
C14 "Comment" C_1210_3225METRIC 2587.2,2672.7 r0 top value=10uF
C15 "Comment" C_1210_3225Metric 2670.87,2999.47 r0 top value=10uF
C16 "Comment" CP_ELEC_10X12.6 1529.13,2920.73 r180 top value=100uF
C17 "Comment" CP_ELEC_10X12.6 2094.09,3019.16 r180 top value=100uF
C18 "Comment" CP_Elec_10x12.6 8214.57,3346.46 r0 top value=100uF
C19 "Comment" C_1210_3225Metric 7769.3,259.33 r0 top value=10uF
C20 "Comment" C_1210_3225Metric 1434.65,3806.56 r90 top value=10uF
C21 "Comment" CP_Elec_10x12.6 9586.61,1190.94 r90 top value=180uF
C22 "Comment" CP_Elec_10x12.6 7362.2,177.72 r90 top value=180uF
C23 "Comment" CP_Elec_10x12.6 8809.06,1305.12 r90 top value=180uF
C24 "Comment" C_1210_3225Metric 6076.38,259.33 r0 top value=10uF
C25 "CL10B104KC8NNNC" C_0603 1943.5,819.35 r0 top value=100nF
C26 "CL10B104KC8NNNC" C_0603 2063.58,1295.73 r0 top value=100nF
C27 "CL10B104KC8NNNC" C_0603 1453.35,835.1 r180 top value=100nF
C28 "CL10B104KC8NNNC" C_0603 1502.56,1297.7 r180 top value=100nF
C29 "CL10B104KC8NNNC" C_0603 1592.13,2070.34 r180 top value=100nF
C30 "CL21B106KPQNFNE" C_0805 13454.72,5356.3 r270 top value=10uF
C31 "CL10B104KC8NNNC" C_0603 13375.98,5364.17 r270 top value=100nF
C32 "CL21B106KPQNFNE" C_0805 2060.63,1779 r0 top value=10uF
C33 "CL10B104KC8NNNC" C_0603 2670.87,1779 r0 top value=100nF
C34 "CL10B104KC8NNNC" C_0603 5987.78,249.49 r90 top value=100nF
C35 "CL21B106KPQNFNE" C_0805 2666.93,952.23 r90 top value=10uF
D1 "B1931USD-20D000814U1930" LED_0603 720,5125 r90 top
D2 "B1931USD-20D000814U1930" LED_0603 20020,345 r0 top
D3 "B1931NG--20D001114U1930" LED_0603 8110.24,1820.87 r90 top
D4 "B1931NG--20D001114U1930" LED_0603 18145,335 r90 top
D5 "B1931NG--20D001114U1930" LED_0603 4184,4150.56 r270 top
D6 "Comment" D_SOD-123F 6666.91,1804.6 r0 top value=D
D7 "Comment" D_SOD-123F 13736.22,5393.7 r0 top value=D
D8 "Comment" D_SOD-123F 11511.81,5393.7 r0 top value=D
D9 "Comment" D_SOD-123F 11535.43,4192.91 r0 top value=D
D10_EFUSE0 "B1931USD-20D000814U1930" LED_0603 13434.06,2006.89 r90 top (schematic designator D10)
D10_EFUSE1 "B1931USD-20D000814U1930" LED_0603 13868.11,2007.87 r90 top (schematic designator D10)
D10_EFUSE2 "B1931USD-20D000814U1930" LED_0603 14301.18,2007.87 r90 top (schematic designator D10)
D10_EFUSE3 "B1931USD-20D000814U1930" LED_0603 14734.25,2007.87 r90 top (schematic designator D10)
D11 "D_TVS" D_SMA 3897.64,787.4 r90 top
D12 "Comment" D_SMA 4094.49,787.4 r90 top value=D_TVS
D13 "Comment" D_SMA 4218.5,3440.46 r180 top value=D_TVS
D14 "Comment" D_SMA 9586.61,5777.56 r90 top value=D_TVS
D15 "Comment" D_SMA 6076.36,1460.12 r90 top value=D_TVS
D16 "Comment" D_SMA 9803.15,5787.4 r90 top value=D_TVS
D17 "Comment" D_SMA 10629.92,5433.07 r90 top value=D_TVS
D18 "Comment" D_SMA 10039.37,5787.4 r90 top value=D_TVS
D19 "Comment" D_SMA 26940,265 r90 top value=D_TVS
D20 "SMAZ36-13-F" SMAZ36-13-F 25610,265 r90 top
D21 "SMAZ36-13-F" SMAZ36-13-F 25830,265 r90 top
D22 "SMAZ36-13-F" SMAZ36-13-F 26060,265 r90 top
D23 "Comment" D_SOD-123F 26270,265 r90 top value=D
D24 "Comment" D_SOD-123F 25380,265 r90 top value=D
D25 "Comment" D_SOD-123F 20340,245 r0 top value=D
D26 "B1931NG--20D001114U1930" LED_0603 20045,265 r90 top
D27 "B1931UY--20D000114U1930" LED_0603 16460,335 r90 top
D28 "B1931USD-20D000814U1930" LED_0603 15720,350 r90 top
D29 "B1931NB--20C007614U1930" LED_0603 15075,245 r0 top
D30 "Comment" D_SMA 14165,335 r90 top value=D_TVS
D31 "SMAZ36-13-F" SMAZ36-13-F 14400,335 r90 top
D32 "Comment" D_SOD-123F 13440,350 r90 top value=D
D33 "Comment" D_SMA 13650,350 r90 top value=D_TVS
D34 "Comment" D_SMA 13930,335 r90 top value=D_TVS
D35 "Comment" D_SMA 13210,350 r90 top value=D_TVS
D36 "Comment" D_SMA 12775,245 r0 top value=D_TVS
D37 "Comment" D_SMA 13010,245 r0 top value=D_TVS
D38 "Comment" D_SMA 10787.4,1299.21 r90 top value=D_TVS
D39 "Comment" D_SMA 12325,335 r90 top value=D_TVS
F1 "Comment" 3557-10 8389.24,45 r90 top value=3557-10
F2 "0ZCF0185FF2C" 0ZCF 236.22,5669.29 r0 top
F3 "Comment" FUSC9830X318N -393.7,6043.31 r0 top value=Fuse
F4 "Comment" FUSC9830X318N 8895.79,2165.35 r0 top value=Fuse
F5 "F0603G0R10FNTR" FUSE_0603 6666.91,2227.83 r0 top
F6 "F0603G0R10FNTR" FUSE_0603 6027.15,2001.45 r0 top
F7 "F0603G0R10FNTR" FUSE_0603 6027.15,1135.31 r0 top
F8 "F0603G0R10FNTR" FUSE_0603 6863.76,1794.76 r0 top
F9 "F0603G0R10FNTR" FUSE_0603 6233.84,1794.76 r0 top
F10 "0ZCF0185FF2C" 0ZCF 8120.08,875.98 r90 top
F11 "F0603G0R10FNTR" FUSE_0603 6538.96,1351.85 r0 top
IC1 "SI2318CDS-T1-GE3" SOT95P237X112-3N 11505.91,4881.89 r0 top
IC2 "SI2318CDS-T1-GE3" SOT95P237X112-3N 11496.06,5078.74 r270 top
IC3 "SI2318CDS-T1-GE3" SOT95P237X112-3N 11498.03,5263.78 r0 top
IC4 "SI2318CDS-T1-GE3" SOT95P237X112-3N 11535.43,4055.12 r0 top
IC5 "Comment" SOT95P237X112-3N 6102.36,5196.85 r0 top value=SI2318CDS-T1-GE3
IC6 "Comment" SOT95P237X112-3N 6037.01,967.99 r0 top value=SI2318CDS-T1-GE3
IC7 "Comment" SOT95P237X112-3N 10960,265 r0 top value=SI2318CDS-T1-GE3
IC8 "Comment" SOT95P237X112-3N 10025,265 r0 top value=SI2318CDS-T1-GE3
J1 "39-29-3046" 39-29-3046 1082.68,5755.91 r0 top
J2 "Comment" PINHEADER_2X20_P2.54MM_HORIZONTAL 5402.63,2951.37 r0 top value=Conn_02x20_Odd_Even
J3 "Comment" PinHeader_2x20_P2.54mm_Vertical 3228.35,393.7 r90 top value=Conn_02x20_Odd_Even
J4 "39-30-1039" 39-30-1039 5072.31,4041.11 r90 top
J5 "43650-0428" 43650-0428 7955.59,2113.43 r0 top
J6 "Comment" CUI_PJ-063BH 7411.42,1515.75 r90 top value=PJ-063BH
J7 "43650-0627" 43650-0627 6409.45,2480.32 r90 top
J8 "43650-0527" 43650-0527 6338.58,5708.66 r0 top
J9 "43045-0428" 43045-0428 5071.19,2952.38 r0 top
J10 "43650-0328" 43650-0328 4409.45,748.03 r0 top
J11 "43045-1228" 43045-1228 11299.21,2007.87 r0 top
J12 "43650-0228" 43650-0228 7047.24,4055.12 r0 top
PS1 "OKI-78SR-5/1.5-W36E-C" OKI-78SR-5&slash_1.5-W36E-C 196.85,4918.11 r90 top
PS2 "Comment" CONV_I7C4W008A120V-0C3-R 2386.81,2675.65 r270 bottom value=I7C4W008A120V-0C3-R
PS3 "Comment" CONV_I7C4W008A120V-0C3-R 1787.2,2069.35 r90 bottom value=I7C4W008A120V-0C3-R
PS4 "OKI-78SR-3.3/1.5-W36E-C" OKI-78SR-5&slash_1.5-W36E-C 6807.76,94.8 r90 top
R1 "RNCF0603BTE4K64" R_0603 20730,240 r0 top value=4.64k
R2 "RMCF0603FG1K00" R_0603 130,1486.56 r90 top value=1k
R3 "RMCF0603FT2K00" C_0603 19060,240 r0 top value=2kR
R4 "RMCF0603FT28R0" R_0603 18360,240 r0 top value=28
R5 "RMCF0603FG1K00" R_0603 17282.42,435 r0 top value=1k
R6 "RMCF0603FT2K00" C_0603 8110.24,1535.43 r90 top value=2kR
R7 "RMCF0603FT10K0" R_0603 4617.87,2925.14 r180 top value=10k
R8 "RMCF0603FT10K0" R_0603 4823.07,2925.14 r0 top value=10k
R9 "RMCF0603FT10K0" R_0603 4617.87,2732.7 r180 top value=10k
R10 "RMCF0603FT10K0" R_0603 4823.07,2732.7 r0 top value=10k
R11 "RMCF0603FT10R0" R_0603 6460.22,2217.99 r0 top value=10R
R12 "RMCF0603FT10R0" R_0603 6214.16,2247.51 r90 top value=10R
R13 "RMCF0603FT10R0" R_0603 10740,240 r0 top value=10R
R14 "RMCF0603FT10R0" R_0603 5997.62,2247.51 r90 top value=10R
R15 "RMCF0603FT10R0" R_0603 7530,240 r0 top value=10R
R16 "RMCF0603FT10K0" R_0603 7290,240 r0 top value=10k
R17 "Comment" R_1206_3216Metric 10500,240 r0 top value=10k
R18 "Comment" R_1206_3216Metric 10260,240 r0 top value=10k
R19 "Comment" R_1206_3216Metric 9800,240 r0 top value=10k
R20 "Comment" R_1206_3216METRIC 1936.42,3904.79 r0 top value=10k
R21 "Comment" R_1206_3216METRIC 1434.65,3605.77 r270 top value=10k
R22 "Comment" R_1206_3216METRIC 4728.79,3447.5 r0 top value=10k
R23 "Comment" R_1206_3216METRIC 4728.79,3353.01 r0 top value=10k
R24 "Comment" R_1206_3216METRIC 4728.79,3258.53 r0 top value=10k
R25 "Comment" R_1206_3216METRIC 4728.79,3541.99 r0 top value=220k
R26 "Comment" R_1206_3216METRIC 5454.68,3513.84 r180 top value=220k
R27 "Comment" R_1206_3216METRIC 5454.68,3801.24 r180 top value=10k
R28 "Comment" R_1206_3216METRIC 5454.68,3609.64 r180 top value=10k
R29 "Comment" R_1206_3216METRIC 5454.68,3705.44 r180 top value=220k
R30 "Comment" R_1206_3216METRIC 2217.99,708.41 r180 top value=220k
R31 "Comment" R_1206_3216METRIC 2557.48,952.23 r90 top value=10k
R32 "Comment" R_1206_3216Metric 4421.65,3440.46 r180 top value=10k
R33 "RMCF0603FT2K00" C_0603 11801.18,5295.28 r180 top value=2kR
R34 "RMCF0603FT2K00" C_0603 11801.18,5226.38 r180 top value=2kR
R35 "RMCF0603FT2K00" C_0603 12185.04,5433.07 r180 top value=2kR
R36 "RMCF0603FT2K00" C_0603 12132.45,5493.31 r180 top value=2kR
R37 "RMCF0603FT2K00" C_0603 12185.04,5196.85 r180 top value=2kR
R38 "RMCF0603FT2K00" C_0603 12125.98,5265.75 r180 top value=2kR
R39 "RMCF0603FT2K00" C_0603 12185.04,5048.03 r180 top value=2kR
R40 "RMCF0603FT2K00" C_0603 12125.98,5108.27 r180 top value=2kR
R41 "RMCF0603FT10K0" R_0603 11368.11,4881.89 r270 top value=10k
R42 "RMCF0603FT2K00" C_0603 12185.04,4911.42 r180 top value=2kR
R43 "RMCF0603FT2K00" C_0603 12123.35,4971.65 r180 top value=2kR
R44 "RMCF0603FT2K00" C_0603 12185.04,4783.46 r180 top value=2kR
R45 "RMCF0603FT2K00" C_0603 12122.66,4843.7 r180 top value=2kR
R46 "RMCF0603FT2K00" C_0603 12185.04,4655.51 r0 top value=2kR
R47 "RMCF0603FT2K00" C_0603 12122.74,4715.75 r180 top value=2kR
R48 "RMCF0603FT2K00" C_0603 13838.58,4250.31 r180 top value=2kR
R49 "RMCF0603FT2K00" C_0603 13976.38,4251.97 r0 top value=2kR
R50 "RMCF0603FT2K00" C_0603 13838.58,4163.39 r180 top value=2kR
R51 "RMCF0603FT2K00" C_0603 13976.38,4163.39 r0 top value=2kR
R52 "RMCF0603FT2K00" C_0603 13838.58,4064.96 r180 top value=2kR
R53 "RMCF0603FT2K00" C_0603 13976.38,4064.96 r0 top value=2kR
R54 "RMCF0603FT10K0" R_0603 6184.63,229.8 r0 top value=10k
R55 "RMCF0603FT2K00" C_0603 13838.58,3986.22 r180 top value=2kR
R56 "RMCF0603FT2K00" C_0603 13976.38,3986.22 r180 top value=2kR
R57 "RMCF0603ZT0R00" R_0603 11574.8,4468.5 r0 top value=0R
R58 "RMCF0603ZT0R00" R_0603 11574.8,4403.15 r0 top value=0R
R59 "RMCF0603FT2K00" C_0603 13838.58,3877.95 r180 top value=2kR
R60 "RMCF0603FT2K00" C_0603 13976.38,3877.95 r180 top value=2kR
R61 "RMCF0603FT2K00" C_0603 13838.58,3769.69 r180 top value=2kR
R62 "RMCF0603FT2K00" C_0603 13976.38,3769.69 r0 top value=2kR
R63 "RMCF0603FT10K0" R_0603 6017.31,229.8 r0 top value=10k
R64 "RMCF0603FT2K00" C_0603 13946.85,3582.68 r0 top value=2kR
R65 "RMCF0603FT2K00" C_0603 13887.8,3651.57 r0 top value=2kR
R66 "RMCF0603FT2K00" C_0603 13946.85,3444.88 r0 top value=2kR
R67 "RMCF0603FT2K00" C_0603 13887.8,3514.96 r0 top value=2kR
R68 "RMCF0603FT220K" R_0603 6371.64,1814.44 r90 top value=220k
R69 "RMCF0603FT2K00" C_0603 13946.85,3307.09 r0 top value=2kR
R70 "RMCF0603FT2K00" C_0603 13887.8,3375.98 r0 top value=2kR
R71 "RMCF0603FT30K0" R_0603 6017.31,1784.92 r0 top value=30kR
R72_EFUSE0 "RMCF0603FT2K00" C_0603 12434.63,2099.88 r90 top value=2kR (schematic designator R72)
R72_EFUSE1 "RMCF0603FT2K00" C_0603 12434.63,2375.47 r90 top value=2kR (schematic designator R72)
R72_EFUSE2 "RMCF0603FT2K00" C_0603 5987.78,3064.44 r90 top value=2kR (schematic designator R72)
R72_EFUSE3 "RMCF0603FT2K00" C_0603 5987.78,3340.03 r90 top value=2kR (schematic designator R72)
R73_EFUSE0 "RMCF0603FT30K0" R_0603 13709.65,2006.89 r270 top value=30kR (schematic designator R73)
R73_EFUSE1 "RMCF0603FT30K0" R_0603 14143.7,2007.87 r270 top value=30kR (schematic designator R73)
R73_EFUSE2 "RMCF0603FT30K0" R_0603 14576.77,2007.87 r270 top value=30kR (schematic designator R73)
R73_EFUSE3 "RMCF0603FT30K0" R_0603 15009.84,2007.87 r270 top value=30kR (schematic designator R73)
R74_EFUSE0 "RMCF0603ZT0R00" R_0603 13601.38,2006.89 r270 top value=0R (schematic designator R74)
R74_EFUSE1 "RMCF0603ZT0R00" R_0603 14035.43,2007.87 r270 top value=0R (schematic designator R74)
R74_EFUSE2 "RMCF0603ZT0R00" R_0603 14468.5,2007.87 r270 top value=0R (schematic designator R74)
R74_EFUSE3 "RMCF0603ZT0R00" R_0603 14901.57,2007.87 r270 top value=0R (schematic designator R74)
R75 "RMCF0603FT2K00" C_0603 5997.64,259.33 r90 top value=2kR
R76 "RMCF0603FT2K00" C_0603 6233.86,259.33 r90 top value=2kR
R77 "RMCF0603FT2K00" C_0603 17535,245 r90 top value=2kR
R78 "RMCF0603FT2K00" C_0603 17075,250 r90 top value=2kR
SW1 "PSA-0047" SW_TL3305BF260QG 4276.34,3712.5 r90 top value=SW_Push
TP15 "Comment" TestPoint_Pad_D1.0mm 6696.44,505.39 r0 top value="KeySwitch IN"
TP16 "Comment" TestPoint_Pad_D1.0mm 6233.84,505.39 r0 top value="KeySwitch IN"
TP17 "Comment" TestPoint_Pad_D1.0mm 6470.06,505.39 r0 top value="KeySwitch IN"
TP18 "Comment" TestPoint_Pad_D1.0mm 6007.46,505.39 r0 top value="KeySwitch IN"
TP19 "Comment" TestPoint_Pad_D1.0mm 7414.97,771.14 r0 top value="KeySwitch IN"
TP20 "Comment" TestPoint_Pad_D1.0mm 7651.19,771.14 r0 top value="KeySwitch IN"
TP21 "Comment" TestPoint_Pad_D1.0mm 7178.75,771.14 r0 top value="KeySwitch IN"
TP22 "Comment" TestPoint_Pad_D1.0mm 6007.46,761.3 r0 top value="KeySwitch IN"
TP23 "Comment" TestPoint_Pad_D1.0mm 6706.3,771.14 r0 top value="KeySwitch IN"
TP24 "Comment" TestPoint_Pad_D1.0mm 6470.08,771.14 r0 top value="KeySwitch IN"
TP25 "Comment" TestPoint_Pad_D1.0mm 6233.86,771.14 r0 top value="KeySwitch IN"
TP26 "Comment" TestPoint_Pad_D1.0mm 6037.01,771.14 r0 top value="KeySwitch IN"
TP27 "Comment" TestPoint_Pad_D1.0mm 6037.01,1558.54 r0 top value="KeySwitch IN"
TP28 "Comment" TestPoint_Pad_D1.0mm 6233.86,1558.54 r0 top value="KeySwitch IN"
TP29 "Comment" TestPoint_Pad_D1.0mm 6470.06,1027.05 r0 top value="KeySwitch IN"
TP30 "Comment" TestPoint_Pad_D1.0mm 6696.44,1027.05 r0 top value="KeySwitch IN"
TP31 "Comment" TestPoint_Pad_D1.0mm 6233.84,1027.05 r0 top value="KeySwitch IN"
TP32 "Comment" TestPoint_Pad_D1.0mm 6007.46,1027.05 r0 top value="KeySwitch IN"
TP33 "Comment" TestPoint_Pad_D1.0mm 12926.78,1322.32 r0 top value="KeySwitch IN"
TP34 "Comment" TestPoint_Pad_D1.0mm 13163,1322.32 r0 top value="KeySwitch IN"
TP35 "Comment" TestPoint_Pad_D1.0mm 6657.07,810.51 r0 top value="KeySwitch IN"
TP36 "Comment" TestPoint_Pad_D1.0mm 11358.27,5039.37 r0 top value="KeySwitch IN"
TP37 "Comment" TestPoint_Pad_D1.0mm 11643.7,5255.91 r0 top value="KeySwitch IN"
TP38 "Comment" TestPoint_Pad_D1.0mm 11338.58,5393.7 r0 top value="KeySwitch IN"
TP39 "Comment" TestPoint_Pad_D1.0mm 6233.86,1322.32 r0 top value="KeySwitch IN"
TP40 "Comment" TestPoint_Pad_D1.0mm 11377.95,4212.6 r0 top value="KeySwitch IN"
TP41 "Comment" TestPoint_Pad_D1.0mm 6233.86,259.33 r0 top value="KeySwitch IN"
TP42 "Comment" TestPoint_Pad_D1.0mm 6007.46,239.64 r0 top value="KeySwitch IN"
TP43_EFUSE0 "Comment" TestPoint_Pad_D1.0mm 13474.41,2135.83 r90 top value="KeySwitch IN" (schematic designator TP43)
TP43_EFUSE1 "Comment" TestPoint_Pad_D1.0mm 13907.48,2135.83 r0 top value="KeySwitch IN" (schematic designator TP43)
TP43_EFUSE2 "Comment" TestPoint_Pad_D1.0mm 14330.71,2135.83 r0 top value="KeySwitch IN" (schematic designator TP43)
TP43_EFUSE3 "Comment" TestPoint_Pad_D1.0mm 14753.94,2135.83 r0 top value="KeySwitch IN" (schematic designator TP43)
U1 "Line Transceiver, 1 Func, 1 Driver, 1 Rcvr, PDSO8" 8-SOIC 7519.68,4055.12 r90 top
U2 "Comment" SOT-23 2761.1,2301.87 r180 top value=MCP9700T-ETT
U3 "Comment" SOT-23 5394.84,344.59 r90 top value=MCP9700T-ETT
U4 "Comment" TSSOP-16_4.4x5mm_P0.65mm 3247.52,4440.39 r0 top value=74HC4051
U5 "SC0915" MODULE_SCO915_Custom_HeaderStyle 12524.29,5533.83 r0 top
U6_EFUSE0 "NIV3071MTW3TWG" 16-WQFN-5x6 13651.57,2283.46 r0 top (schematic designator U6)
U6_EFUSE1 "NIV3071MTW3TWG" 16-WQFN-5x6 14084.65,2283.46 r0 top (schematic designator U6)
U6_EFUSE2 "NIV3071MTW3TWG" 16-WQFN-5x6 14498.03,2283.46 r0 top (schematic designator U6)
U6_EFUSE3 "NIV3071MTW3TWG" 16-WQFN-5x6 14951.77,2283.46 r0 top (schematic designator U6)

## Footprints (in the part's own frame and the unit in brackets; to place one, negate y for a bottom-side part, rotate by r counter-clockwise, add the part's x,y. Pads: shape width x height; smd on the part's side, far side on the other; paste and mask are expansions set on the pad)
0ZCF [mm]
  rect 2.3x5.6 smd: 1(0,0) 2(7.4,0)
  silkscreen extent -1.5,-3.1 8.9,3.1, body extent -0.1,-2.65 7.5,2.65, height 1.02
8-SOIC [mm]
  rect 2.2x0.7 smd: 1(0,0) 2(0,-1.27) 3(0,-2.54) 4(0,-3.81) 5(5.5,-3.81) 6(5.5,-2.54) 7(5.5,-1.27) 8(5.5,0)
  silkscreen extent -2.13,-4.44 4,1.35, body extent -0.19,-4.35 5.79,0.55, height 1.5
16-WQFN-5x6 [mm]
  rect 0.52x0.35 smd mask+0.05: 1(-2.475,1.575) 2(-2.475,0.525) 3(-2.475,-0.525) 4(-2.475,-1.575) 9(2.475,-1.575) 10(2.475,-0.525) 11(2.475,0.525) 12(2.475,1.575)
  rect 0.35x0.52 smd mask+0.05: 5(-1.575,-2.975) 6(-0.525,-2.975) 7(0.525,-2.975) 8(1.575,-2.975) 13(1.575,2.975) 14(0.525,2.975) 15(-0.525,2.975) 16(-1.575,2.975)
  rect 2.85x4.75 smd mask+0.05: 17(0,0)
  silkscreen extent -2.64,-3.13 2.64,3.14, body extent -2.64,-3.13 2.64,3.14, height 0.8
39-29-3046 [mm]
  round 2.4 hole 1.4: 1(0,0) 2(5.5,0) 3(0,-4.2) 4(5.5,-4.2)
  silkscreen extent -2,-6 7.5,2.6, body extent -2.3,-7.3 8.7,3.1, height 3.5
39-30-1039 [mm]
  round 2.4 hole 1.4: 1(0,0) 2(0,-4.2) 3(0,-8.4)
  silkscreen extent -1.96,-10.4 2.02,2, body extent -6.68,-11.1 4.88,2.7, height 12.45
3557-10 [mil]
  rect 118.11x83 hole 31.5 slot 63 at 0 deg: 1(0,0)
  rrect100% 118.11x83 hole 31.5 slot 63 at 0 deg: 2(0,-134) 3(530,-134) 4(530,0)
  silkscreen extent -130,-204 660,71, body extent -133,-204 655,72, height 96
43045-0428 [mm]
  round 2.14 hole 1.07: 1(0,0) 2(3,0) 3(0,-3) 4(3,-3)
  silkscreen extent -2,-4.5 5,1.5, body extent -2.37,-6.57 6.4,3.57, height 9.95
43045-1228 [mm]
  round 2.14 hole 1.07: 1(0,0) 2(3,0) 3(0,-3) 4(3,-3) 5(0,-6) 6(3,-6) 7(0,-9) 8(3,-9) 9(0,-12) 10(3,-12) 11(0,-15) 12(3,-15)
  silkscreen extent -2,-16.5 5,1.5, body extent -2.47,-18.57 6.3,3.57, height 9.95
43650-0228 [mm]
  round 2.14 hole 1.07: 1(0,0) 2(0,-3)
  silkscreen extent -1.96,-6 2,3, body extent -2.51,-6.32 3.06,3.32, height 10
43650-0328 [mm]
  round 2.14 hole 1.07: 1(0,0) 2(0,-3) 3(0,-6)
  silkscreen extent -1.96,-9 2.01,3, body extent -2.41,-9.25 3.16,3.4, height 10
43650-0428 [mm]
  round 2.14 hole 1.07: 1(0,0) 2(0,-9) 2(0,-6) 2(0,-3)
  silkscreen extent -1.96,-12 2.03,3, body extent -2.43,-12.29 3.14,3.36, height 10
43650-0527 [mm]
  round 2.14 hole 1.07: 1(0,0) 2(0,-3) 3(0,-6) 4(0,-9) 5(0,-12)
  silkscreen extent -1.96,-15 1.96,3, body extent -2.47,-15.32 3.14,3.32, height 9.9
43650-0627 [mm]
  round 2.14 hole 1.07: 1(0,0) 2(0,-3) 3(0,-6) 4(0,-9) 5(0,-12) 6(0,-15)
  silkscreen extent -1.96,-18 1.96,3, body extent -2.45,-18.29 3.12,3.35, height 10
C_0603 [mm]
  rect 0.8x0.8 smd: 1(-0.75,0) 2(0.75,0)
  silkscreen extent -1.4,-0.64 1.4,0.64, body extent -0.85,-0.44 0.85,0.44, height 0.89
C_0805 [mm]
  rect 0.9x1.3 smd: 1(-0.95,0) 2(0.95,0)
  silkscreen extent -1.65,-0.89 1.65,0.89, body extent -1,-0.67 1,0.67, height 1.22
C_1210_3225Metric [mm]
  rrect22% 1.15x2.7 smd mask+0: 1(-1.475,0) 2(1.475,0)
  silkscreen extent -0.71,-1.36 0.71,1.36, body extent -1.6,-1.25 1.6,1.25, height 2.5
C_1210_3225METRIC [mm]
  rrect22% 1.15x2.7 smd mask+0: 1(-1.475,0) 2(1.475,0)
  silkscreen extent -0.71,-1.36 0.71,1.36, body extent -1.6,-1.25 1.6,1.25, height 2.5
CONV_I7C4W008A120V-0C3-R [mm]
  rect 3x3 hole 1.22 paste-2539.97 mask+0: 1(0,0)
  round 2.5 hole 1.22 paste-2539.97 mask+0: 2(0,7.62) 5(-27.94,11.43) 6(-27.94,7.62) 7(-27.94,3.81) 32(-12.07,15.24) 34(-15.88,15.24)
  round 3 hole 1.22 paste-2539.97 mask+0: 3(0,15.24)
  round 3.5 hole 1.77 paste-2539.97 mask+0: 4(-27.94,15.24) 8(-27.94,0)
  silkscreen extent -31.54,-10.8 3.91,26.03, body extent -31.5,-10.79 2.54,26.04, height 13.46
CP_Elec_10x12.6 [mm]
  rrect13% 4.4x1.9 smd mask+0: 1(-4.35,0) 2(4.35,0)
  silkscreen extent -6.75,-5.26 5.26,5.26, body extent -5.85,-5.12 5.85,5.18, height 10.5
CP_ELEC_10X12.6 [mm]
  rrect13% 4.4x1.9 smd mask+0: 1(-4.35,0) 2(4.35,0)
  silkscreen extent -6.75,-5.26 5.26,5.26
CUI_PJ-063BH [mm]
  rrect100% 3x5 hole 3 slot 1 at 0 deg: 1(0,0)
  rrect100% 3x4.5 hole 2.3 slot 1 at 0 deg: 2(6,0)
  rrect100% 4x2.5 hole 1 slot 2.5 at 0 deg: S1(7,4.5) S2(7,-4.5)
  round 1.6 hole 1.6: Un1(9,0)
  silkscreen extent -2,-5 12,5, body extent -0.96,-5.52 12.04,4.78, height 9
D_SMA [mm]
  rrect14% 2.5x1.8 smd mask+0: 1(-2,0) 2(2,0)
  silkscreen extent -3.51,-1.65 2,1.65
D_SOD-123F [mm]
  rrect23% 1.1x1.1 smd mask+0: 1(-1.4,0) 2(1.4,0)
  silkscreen extent -2.21,-1 1.65,1
FUSC9830X318N [mm]
  rect 2.62x3.2 smd: 1(-4.047,0) 2(4.047,0)
  silkscreen extent -2.47,-1.52 2.47,1.52, body extent -4.85,-1.63 4.95,1.55, height 2.83
FUSE_0603 [mm]
  rect 0.85x1.1 smd: 1(-0.775,0) 2(0.775,0)
  silkscreen extent -1.43,-0.77 1.43,0.77, body extent -0.88,-0.48 0.88,0.48, height 0.89
LED_0603 [mm]
  rect 0.8x0.8 smd: 1(-0.75,0) 2(0.75,0)
  silkscreen extent -1.77,-0.63 1.38,0.63, body extent -0.8,-0.41 0.8,0.41, height 0.41
MODULE_SCO915_Custom_HeaderStyle [mm]
  rect 1.7x1.7 hole 1: 1(0.853,-0.859) 40(18.633,-0.859)
  rrect100% 1.7x1.7 hole 1: 2(0.853,-3.399) 3(0.875,-5.95) 4(0.853,-8.479) 5(0.853,-11.019) 6(0.853,-13.559) 7(0.853,-16.099) 8(0.853,-18.639) 9(0.853,-21.179) 10(0.853,-23.719) 11(0.853,-26.259) 12(0.853,-28.799) 13(0.853,-31.339) 14(0.853,-33.879) 15(0.853,-36.419) 16(0.853,-38.959) 17(0.853,-41.499) 18(0.853,-44.039) 19(0.853,-46.579) 20(0.853,-49.119) 21(18.633,-49.119) 22(18.633,-46.579) 23(18.633,-44.039) 24(18.633,-41.499) 25(18.633,-38.959) 26(18.633,-36.419) 27(18.633,-33.879) 28(18.633,-31.339) 29(18.633,-28.799) 30(18.633,-26.259) 31(18.633,-23.719) 32(18.633,-21.179) 33(18.633,-18.639) 34(18.633,-16.099) 35(18.633,-13.559) 36(18.633,-11.019) 37(18.633,-8.479) 38(18.633,-5.939) 39(18.633,-3.399)
  silkscreen extent -0.48,-50.45 19.96,0.47, body extent -0.75,-50.67 20.25,1.65, height 14.73
OKI-78SR-5&slash_1.5-W36E-C [mm]
  rrect100% 1.75x3 hole 1.067: 1(0,0) 2(2.54,0) 3(5.08,0)
  silkscreen extent -3.81,-8.51 8.89,2.41, body extent -3.73,-8.38 8.71,2.29, height 18.13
